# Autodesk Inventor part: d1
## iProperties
Created: 2002-02
Part Number: d1
Document SubType Name: ﾓﾃﾞﾘﾝｸﾞ
Designer: Administrator
Control State: 0
Master: False
Checked Out: False
Shininess: 64.0
Length Units: 11269
Angle Units: 11279
Time Units: 11290
Mass Units: 11284
Length Display Precision: 2
Angle Display Precision: 1
Density: 0.0
Volumn: 0.0
Area: 0.0
PropertySet Name: Model Information
Author: Administrator
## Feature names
1. 押し出し1 [Extrusion]
2. 押し出し5 [Extrusion]
